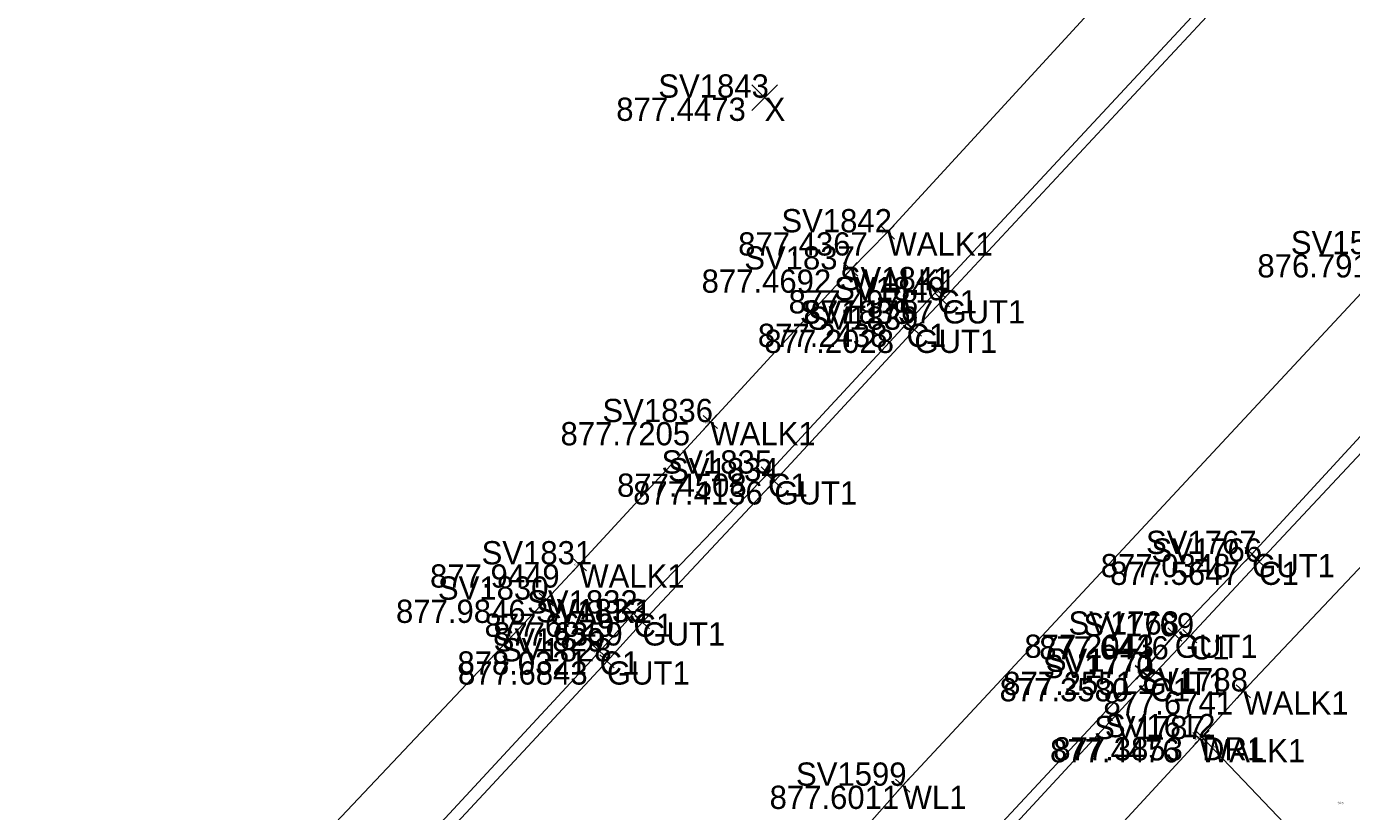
# Model space of a CAD drawing. Extents: x 1469677 to 1493262, y 375219 to 389293.
# Drawn here: x 1480035.5 to 1480103.9, y 379307 to 379347.5 of the extents above; entities that cross this region are included whole.
import ezdxf

# ---------------------------------------------------------------- set-up
doc = ezdxf.new("R2010")
doc.units = 0
for name, color, linetype in [('DR_X_Drive_Pipe', 7, 'Continuous'), ('DV_X_Lot_Line', 7, 'Continuous'), ('DV_X_Text', 7, 'Continuous'), ('GK_Visualization', 7, 'Continuous'), ('PNTELEV', 7, 'Continuous'), ('RD_P_Text', 7, 'Continuous'), ('RW_P_Esmt_SW', 7, 'Continuous'), ('RW_P_Esmt_U', 7, 'Continuous'), ('Text Border', 7, 'Continuous')]:
    doc.layers.add(name, color=color, linetype=linetype)

msp = doc.modelspace()

# ---------------------------------------------------------------- linework, layer by layer
at = {"layer": 'DR_X_Drive_Pipe'}
msp.add_lwpolyline([(1480169.204, 379397.823), (1480165.761, 379394.087), (1480162.59, 379391.88), (1480159.156, 379388.706), (1480148.911, 379378.819), (1480120.344, 379350.087), (1480106.297, 379335.736), (1480080.736, 379308.289), (1480073.091, 379299.637), (1480056.748, 379281.628), (1480051.266, 379275.974)], dxfattribs=at)
at = {"layer": 'DV_X_Lot_Line'}
for points in [[(1480035.484, 379289.224), (1480050.568, 379305.437), (1480062.335, 379317.896), (1480064.038, 379319.719), (1480070.805, 379327.066), (1480078.054, 379334.946), (1480079.953, 379336.866), (1480094.208, 379352.393), (1480112.048, 379371.575), (1480117.348, 379377.211), (1480119.911, 379379.906), (1480121.511, 379381.77), (1480134.604, 379395.58), (1480136.695, 379398.148), (1480138.778, 379401.149), (1480140.004, 379404.725), (1480140.577, 379408.06), (1480140.982, 379411.311), (1480140.871, 379414.584), (1480140.225, 379417.636), (1480139.184, 379419.586), (1480133.124, 379425.845), (1480132.903, 379425.968), (1480114.834, 379442.96)], [(1480059.793, 379271.54), (1480075.261, 379288.048), (1480088.444, 379302.419), (1480096.088, 379310.695), (1480098.33, 379313.163), (1480111.975, 379327.613), (1480128.977, 379345.933), (1480145.46, 379363.52), (1480153.413, 379372.021), (1480155.772, 379374.786), (1480158.213, 379377.107), (1480160.137, 379378.801), (1480161.631, 379379.994)]]:
    msp.add_lwpolyline(points, dxfattribs=at)
at = {"layer": 'PNTELEV'}
for p, q in [((1480079.598, 379337.218), (1480080.308, 379336.514)), ((1480079.601, 379336.51), (1480080.305, 379337.221)), ((1480079.953, 379336.866), (1480079.953, 379336.866)), ((1480077.686, 379335.285), (1480078.422, 379334.608)), ((1480077.715, 379334.578), (1480078.393, 379335.314)), ((1480078.054, 379334.946), (1480078.054, 379334.946)), ((1480082.16, 379334.215), (1480082.898, 379333.539)), ((1480082.191, 379333.508), (1480082.867, 379334.245)), ((1480082.529, 379333.877), (1480082.529, 379333.877)), ((1480082.432, 379333.702), (1480083.156, 379333.012)), ((1480082.449, 379332.995), (1480083.139, 379333.719)), ((1480082.794, 379333.357), (1480082.794, 379333.357)), ((1480080.573, 379332.483), (1480081.307, 379331.804)), ((1480080.6, 379331.777), (1480081.28, 379332.511)), ((1480080.94, 379332.144), (1480080.94, 379332.144)), ((1480080.978, 379332.175), (1480081.712, 379331.496)), ((1480081.006, 379331.468), (1480081.684, 379332.203)), ((1480081.345, 379331.835), (1480081.345, 379331.835)), ((1480070.437, 379327.405), (1480071.173, 379326.728)), ((1480070.466, 379326.699), (1480071.144, 379327.434)), ((1480070.805, 379327.066), (1480070.805, 379327.066)), ((1480073.422, 379324.754), (1480074.142, 379324.061)), ((1480073.435, 379324.047), (1480074.129, 379324.768)), ((1480073.746, 379324.349), (1480074.476, 379323.666)), ((1480073.769, 379323.643), (1480074.453, 379324.373)), ((1480073.782, 379324.407), (1480073.782, 379324.407)), ((1480074.111, 379324.008), (1480074.111, 379324.008)), ((1480063.697, 379319.354), (1480064.379, 379320.085)), ((1480099.153, 379319.917), (1480098.417, 379320.594)), ((1480099.124, 379320.623), (1480098.446, 379319.887)), ((1480099.511, 379319.516), (1480098.781, 379320.2)), ((1480098.785, 379320.255), (1480098.785, 379320.255)), ((1480099.488, 379320.222), (1480098.804, 379319.493)), ((1480063.673, 379320.061), (1480064.403, 379319.378)), ((1480064.038, 379319.719), (1480064.038, 379319.719)), ((1480099.146, 379319.858), (1480099.146, 379319.858)), ((1480061.971, 379318.239), (1480062.699, 379317.553)), ((1480061.992, 379317.532), (1480062.678, 379318.259)), ((1480062.335, 379317.896), (1480062.335, 379317.896)), ((1480066.459, 379317.514), (1480067.205, 379316.847)), ((1480066.499, 379316.808), (1480067.165, 379317.553)), ((1480066.832, 379317.181), (1480066.832, 379317.181)), ((1480066.926, 379317.063), (1480067.666, 379316.391)), ((1480066.96, 379316.357), (1480067.632, 379317.097)), ((1480067.296, 379316.727), (1480067.296, 379316.727)), ((1480095.154, 379315.746), (1480094.432, 379316.438)), ((1480095.139, 379316.453), (1480094.447, 379315.731)), ((1480094.793, 379316.092), (1480094.793, 379316.092)), ((1480095.935, 379315.668), (1480095.203, 379316.348)), ((1480095.909, 379316.374), (1480095.229, 379315.642)), ((1480095.569, 379316.008), (1480095.569, 379316.008)), ((1480064.716, 379315.563), (1480065.45, 379314.884)), ((1480064.743, 379314.857), (1480065.423, 379315.59)), ((1480065.083, 379315.224), (1480065.083, 379315.224)), ((1480065.098, 379315.051), (1480065.83, 379314.37)), ((1480065.124, 379314.344), (1480065.804, 379315.077)), ((1480065.464, 379314.71), (1480065.464, 379314.71)), ((1480093.501, 379313.844), (1480092.747, 379314.5)), ((1480093.452, 379314.55), (1480092.796, 379313.795)), ((1480093.124, 379314.172), (1480093.124, 379314.172)), ((1480093.894, 379313.503), (1480093.166, 379314.189)), ((1480093.873, 379314.209), (1480093.187, 379313.482)), ((1480093.53, 379313.846), (1480093.53, 379313.846)), ((1480097.96, 379313.499), (1480098.7, 379312.827)), ((1480097.994, 379312.793), (1480098.666, 379313.533)), ((1480098.33, 379313.163), (1480098.33, 379313.163)), ((1480095.721, 379311.034), (1480096.455, 379310.356)), ((1480095.749, 379310.328), (1480096.427, 379311.062)), ((1480096.561, 379311.138), (1480095.837, 379310.448)), ((1480095.854, 379311.155), (1480096.544, 379310.431)), ((1480096.088, 379310.695), (1480096.088, 379310.695)), ((1480096.199, 379310.793), (1480096.199, 379310.793)), ((1480081.102, 379307.949), (1480080.37, 379308.63)), ((1480081.077, 379308.655), (1480080.396, 379307.924)), ((1480080.736, 379308.289), (1480080.736, 379308.289))]:
    msp.add_line(p, q, dxfattribs=at)
at = {"layer": 'RD_P_Text'}
for points in [[(1480155.238, 379379.795), (1480153.548, 379379.014), (1480146.824, 379371.927), (1480145.567, 379370.605), (1480143.964, 379368.78), (1480128.12, 379351.892), (1480112.56, 379335.214), (1480098.785, 379320.255), (1480094.793, 379316.092), (1480093.124, 379314.172), (1480085.166, 379305.624), (1480081.585, 379301.702), (1480079.854, 379299.882), (1480067.172, 379286.11), (1480056.531, 379274.485), (1480055.169, 379272.969)], [(1480155.431, 379379.884), (1480153.98, 379378.667), (1480147.216, 379371.505), (1480146.047, 379370.27), (1480144.119, 379368.047), (1480128.647, 379351.629), (1480112.741, 379334.357), (1480099.146, 379319.858), (1480095.569, 379316.008), (1480093.53, 379313.846), (1480085.356, 379305.01), (1480081.967, 379301.397), (1480080.218, 379299.413), (1480067.589, 379285.613), (1480056.688, 379273.774), (1480055.547, 379272.623)], [(1480038.409, 379286.458), (1480053.445, 379302.656), (1480065.083, 379315.224), (1480066.832, 379317.181), (1480073.782, 379324.407), (1480080.94, 379332.144), (1480082.529, 379333.877), (1480097.272, 379349.731)], [(1480038.979, 379286.174), (1480053.858, 379302.215), (1480065.464, 379314.71), (1480067.296, 379316.727), (1480074.111, 379324.008), (1480081.345, 379331.835), (1480082.794, 379333.357), (1480097.622, 379349.287)]]:
    msp.add_lwpolyline(points, dxfattribs=at)
at = {"layer": 'RW_P_Esmt_U'}
for p, q in [((1480072.94, 379343.152), (1480074.274, 379344.487)), ((1480072.94, 379344.487), (1480074.274, 379343.152))]:
    msp.add_line(p, q, dxfattribs=at)
at = {"layer": 'Text Border'}
msp.add_lwpolyline([(1480096.199, 379310.793), (1480107.531, 379298.913)], dxfattribs=at)

# ---------------------------------------------------------------- texts
at = {"layer": 'DV_X_Text'}
for s, height, p in [('877.4473', 1.2, (1480065.945, 379342.62)), ('877.45', 0.06, (1480073.327, 379343.76)), ('877.4367', 1.2, (1480072.243, 379335.666)), ('877.44', 0.06, (1480079.674, 379336.806)), ('876.7919', 1.2, (1480099.06, 379334.536)), ('877.4692', 1.2, (1480070.354, 379333.746)), ('877.47', 0.06, (1480077.774, 379334.886)), ('877.4978', 1.2, (1480074.848, 379332.677)), ('877.50', 0.06, (1480082.245, 379333.817)), ('877.1757', 1.2, (1480075.623, 379332.157)), ('877.18', 0.06, (1480082.538, 379333.297)), ('877.2438', 1.2, (1480073.259, 379330.944)), ('877.2028', 1.2, (1480073.597, 379330.635)), ('877.24', 0.06, (1480080.662, 379332.084)), ('877.20', 0.06, (1480081.062, 379331.775)), ('877.7205', 1.2, (1480063.067, 379325.866)), ('877.72', 0.06, (1480070.527, 379327.006)), ('877.4508', 1.2, (1480065.987, 379323.207)), ('877.45', 0.06, (1480073.502, 379324.347)), ('877.4136', 1.2, (1480066.818, 379322.808)), ('877.41', 0.06, (1480073.854, 379323.948)), ('877.0348', 1.2, (1480090.971, 379319.055)), ('877.03', 0.06, (1480098.5, 379320.195)), ('877.9449', 1.2, (1480056.328, 379318.519)), ('877.94', 0.06, (1480063.758, 379319.659)), ('877.5647', 1.2, (1480091.455, 379318.658)), ('877.56', 0.06, (1480098.863, 379319.798)), ('877.9846', 1.2, (1480054.569, 379316.696)), ('877.98', 0.06, (1480062.054, 379317.836)), ('877.6629', 1.2, (1480059.141, 379315.981)), ('877.6359', 1.2, (1480059.586, 379315.527)), ('877.66', 0.06, (1480066.548, 379317.121)), ('877.64', 0.06, (1480067.016, 379316.667)), ('877.2043', 1.2, (1480087.027, 379314.892)), ('877.6446', 1.2, (1480087.793, 379314.808)), ('877.20', 0.06, (1480094.51, 379316.032)), ('877.64', 0.06, (1480095.289, 379315.948)), ('878.0321', 1.2, (1480057.739, 379314.024)), ('877.6843', 1.2, (1480057.773, 379313.51)), ('878.03', 0.06, (1480064.797, 379315.164)), ('877.68', 0.06, (1480065.183, 379314.65)), ('877.2551', 1.2, (1480085.932, 379312.972)), ('877.26', 0.06, (1480092.842, 379314.112)), ('877.3580', 1.2, (1480085.745, 379312.646)), ('877.36', 0.06, (1480093.246, 379313.786)), ('877.6741', 1.2, (1480091.109, 379311.963)), ('877.67', 0.06, (1480098.05, 379313.103)), ('877.4476', 1.2, (1480088.35, 379309.495)), ('877.3853', 1.2, (1480088.518, 379309.593)), ('877.45', 0.06, (1480095.808, 379310.635)), ('877.39', 0.06, (1480095.918, 379310.733)), ('877.41', 0.06, (1480096.136, 379310.58)), ('877.44', 0.06, (1480096.333, 379310.843)), ('877.57', 0.06, (1480096.761, 379310.214)), ('877.6011', 1.2, (1480073.866, 379307.089)), ('877.60', 0.06, (1480080.451, 379308.229)), ('878.18', 0.06, (1480103.246, 379307.336))]:
    msp.add_text(s, height=height, dxfattribs=at).set_placement(p)
at = {"layer": 'GK_Visualization'}
for s, p in [('X', (1480073.607, 379342.62)), ('WALK1', (1480079.953, 379335.666)), ('WALK1', (1480078.054, 379333.746)), ('C1', (1480082.529, 379332.677)), ('GUT1', (1480082.794, 379332.157)), ('C1', (1480080.94, 379330.944)), ('GUT1', (1480081.345, 379330.635)), ('WALK1', (1480070.805, 379325.866)), ('C1', (1480073.782, 379323.207)), ('GUT1', (1480074.111, 379322.808)), ('GUT1', (1480098.785, 379319.055)), ('WALK1', (1480064.038, 379318.519)), ('C1', (1480099.146, 379318.658)), ('WALK1', (1480062.335, 379316.696)), ('C1', (1480066.832, 379315.981)), ('GUT1', (1480067.296, 379315.527)), ('GUT1', (1480094.793, 379314.892)), ('C1', (1480095.569, 379314.808)), ('C1', (1480065.083, 379314.024)), ('GUT1', (1480065.464, 379313.51)), ('GUT1', (1480093.124, 379312.972)), ('C1', (1480093.53, 379312.646)), ('WALK1', (1480098.33, 379311.963)), ('WALK1', (1480096.088, 379309.495)), ('DR1', (1480096.199, 379309.593)), ('WL1', (1480080.736, 379307.089))]:
    msp.add_text(s, height=1.2, dxfattribs=at).set_placement(p)
at = {"layer": 'RW_P_Esmt_SW'}
for s, height, p in [('SV1843', 1.2, (1480068.118, 379343.82)), ('SV1843', 0.06, (1480073.333, 379343.82)), ('SV1842', 1.2, (1480074.474, 379336.866)), ('SV1842', 0.06, (1480079.679, 379336.866)), ('SV1598', 1.2, (1480100.789, 379335.736)), ('SV1837', 1.2, (1480072.556, 379334.946)), ('SV1840', 1.2, (1480077.201, 379333.357)), ('SV1841', 1.2, (1480077.492, 379333.877)), ('SV1837', 0.06, (1480077.779, 379334.946)), ('SV1841', 0.06, (1480082.277, 379333.877)), ('SV1838', 1.2, (1480075.432, 379332.144)), ('SV1840', 0.06, (1480082.514, 379333.357)), ('SV1839', 1.2, (1480075.837, 379331.835)), ('SV1838', 0.06, (1480080.665, 379332.144)), ('SV1839', 0.06, (1480081.07, 379331.835)), ('SV1836', 1.2, (1480065.231, 379327.066)), ('SV1836', 0.06, (1480070.526, 379327.066)), ('SV1835', 1.2, (1480068.284, 379324.407)), ('SV1834', 1.2, (1480068.622, 379324.008)), ('SV1835', 0.06, (1480073.507, 379324.407)), ('SV1834', 0.06, (1480073.837, 379324.008)), ('SV1767', 1.2, (1480093.306, 379320.255)), ('SV1831', 1.2, (1480058.991, 379319.719)), ('SV1766', 1.2, (1480093.591, 379319.858)), ('SV1767', 0.06, (1480098.511, 379320.255)), ('SV1831', 0.06, (1480063.786, 379319.719)), ('SV1766', 0.06, (1480098.868, 379319.858)), ('SV1830', 1.2, (1480056.733, 379317.896)), ('SV1832', 1.2, (1480061.343, 379317.181)), ('SV1833', 1.2, (1480061.798, 379316.727)), ('SV1830', 0.06, (1480062.055, 379317.896)), ('SV1832', 0.06, (1480066.558, 379317.181)), ('SV1833', 0.06, (1480067.021, 379316.727)), ('SV1768', 1.2, (1480089.304, 379316.092)), ('SV1769', 1.2, (1480090.08, 379316.008)), ('SV1829', 1.2, (1480059.613, 379315.224)), ('SV1768', 0.06, (1480094.519, 379316.092)), ('SV1769', 0.06, (1480095.295, 379316.008)), ('SV1828', 1.2, (1480059.994, 379314.71)), ('SV1829', 0.06, (1480064.81, 379315.224)), ('SV1771', 1.2, (1480088.134, 379314.172)), ('SV1828', 0.06, (1480065.191, 379314.71)), ('SV1770', 1.2, (1480087.985, 379313.846)), ('SV1771', 0.06, (1480092.874, 379314.172)), ('SV1788', 1.2, (1480092.86, 379313.163)), ('SV1770', 0.06, (1480093.253, 379313.846)), ('SV1788', 0.06, (1480098.057, 379313.163)), ('SV1787', 1.2, (1480090.628, 379310.695)), ('SV1612', 1.2, (1480091.184, 379310.793)), ('SV1787', 0.06, (1480095.815, 379310.695)), ('SV1612', 0.06, (1480095.948, 379310.793)), ('SA2003', 0.06, (1480096.085, 379310.64)), ('SA2011', 0.06, (1480096.356, 379310.903)), ('SA2010', 0.06, (1480096.756, 379310.274)), ('SV1599', 1.2, (1480075.229, 379308.289)), ('SV1599', 0.06, (1480080.461, 379308.289)), ('SA2065', 0.06, (1480103.2, 379307.396))]:
    msp.add_text(s, height=height, dxfattribs=at).set_placement(p)

doc.saveas('drawing.dxf')
